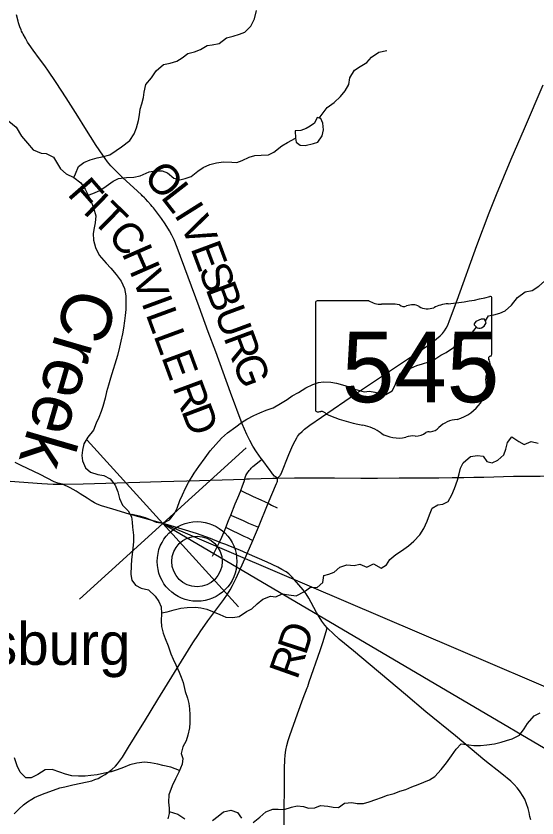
# Model space of a CAD drawing. Extents: x 0 to 70.2, y 0 to 31.4.
# Drawn here: x 5.768 to 6.741, y 16.713 to 18.211 of the extents above; entities that cross this region are included whole.
import ezdxf

# ---------------------------------------------------------------- set-up
doc = ezdxf.new("R2010")
doc.units = 0
for name, color, linetype in [('Default', 7, 'Continuous'), ('GM_X_County_Road', 7, 'Continuous'), ('GM_X_County_Road_Text', 7, 'Continuous'), ('GM_X_Minor_Lake', 7, 'Continuous'), ('GM_X_Minor_River', 7, 'Continuous'), ('GM_X_Minor_River_Text', 7, 'Continuous'), ('GM_X_State_Location', 7, 'Continuous'), ('GM_X_State_Route', 7, 'Continuous'), ('GM_X_State_Shield', 7, 'Continuous'), ('GM_X_Township_Road', 7, 'Continuous'), ('GM_X_Township_Road_Text', 7, 'Continuous'), ('GM_X_Unincorporated', 7, 'Continuous'), ('GM_X_Unincorporated_Location', 7, 'Continuous'), ('GM_X_Unincorporated_Text', 7, 'Continuous'), ('SH_Data', 7, 'Continuous')]:
    doc.layers.add(name, color=color, linetype=linetype)

msp = doc.modelspace()

# ---------------------------------------------------------------- linework, layer by layer
at = {"layer": 'Default'}
msp.add_lwpolyline([(7.3479, 16.7052), (6.0425, 17.2633), (7.3479, 16.4952)], close=True, dxfattribs=at)
at = {"layer": 'GM_X_County_Road'}
for points in [[(6.2277, 17.3831), (6.2266, 17.3845), (6.2176, 17.3972), (6.211, 17.4076), (6.2049, 17.4183), (6.1995, 17.4295), (6.1906, 17.4494), (6.1693, 17.5076), (6.1416, 17.5835), (6.1276, 17.6214), (6.1103, 17.668), (6.0694, 17.7787), (6.0635, 17.7931), (6.0595, 17.8016), (6.055, 17.8098), (6.047, 17.823), (6.0402, 17.8331), (6.0328, 17.843), (6.0251, 17.8525), (6.0227, 17.8552), (6.0201, 17.8586), (6.0145, 17.8648), (6.0102, 17.8695), (6.0083, 17.8715), (6.0041, 17.8754), (6.0028, 17.8768), (5.9877, 17.8905), (5.9677, 17.9089), (5.9552, 17.921), (5.9452, 17.9314), (5.9395, 17.9386), (5.9303, 17.9512), (5.9183, 17.969), (5.8968, 18.0026), (5.8837, 18.0239), (5.862, 18.058), (5.8433, 18.0867), (5.8276, 18.1097), (5.8233, 18.1158), (5.8131, 18.1304), (5.8084, 18.1362), (5.8039, 18.142), (5.8017, 18.1453), (5.796, 18.1532), (5.7901, 18.1624), (5.786, 18.1695), (5.7819, 18.1773), (5.7804, 18.1797), (5.7788, 18.183), (5.7778, 18.1854), (5.7758, 18.1907), (5.7733, 18.1985), (5.7724, 18.2014), (5.7694, 18.2133)], [(6.2568, 17.3479), (6.2532, 17.3501), (6.2509, 17.3519), (6.2476, 17.3559), (6.2451, 17.3595), (6.2433, 17.3621), (6.2277, 17.3831)]]:
    msp.add_lwpolyline(points, dxfattribs=at)
at = {"layer": 'GM_X_Minor_Lake'}
for points in [[(6.2906, 17.9827), (6.2917, 17.9751), (6.2992, 17.9698), (6.3087, 17.9694), (6.3239, 17.9727), (6.3323, 17.9753), (6.3403, 17.987), (6.3426, 17.9984), (6.3412, 18.011), (6.3378, 18.0197), (6.331, 18.0213), (6.326, 18.011), (6.318, 18.0054), (6.3104, 18.0012), (6.3005, 17.9971), (6.2895, 17.9964)], [(6.2895, 17.9964), (6.2906, 17.9827)], [(6.638, 17.6288), (6.6425, 17.6318), (6.6464, 17.6382), (6.6437, 17.6447), (6.6369, 17.6451), (6.627, 17.6406), (6.6243, 17.6361)], [(6.6243, 17.6361), (6.6244, 17.6341), (6.6257, 17.6324), (6.6279, 17.6302), (6.63, 17.6285), (6.6326, 17.628), (6.6355, 17.628), (6.638, 17.6288)]]:
    msp.add_lwpolyline(points, dxfattribs=at)
at = {"layer": 'GM_X_Minor_River'}
for points in [[(5.8762, 17.9092), (5.8797, 17.9164), (5.8851, 17.9297), (5.8953, 17.9376), (5.9071, 17.9421), (5.9201, 17.9462), (5.9295, 17.9481), (5.9436, 17.9518), (5.9554, 17.9601), (5.9657, 17.9669), (5.9809, 17.9782), (5.989, 17.9907), (5.9932, 18.0024), (5.997, 18.0157), (5.999, 18.0263), (6.0002, 18.0369), (6.0033, 18.0471), (6.0063, 18.0585), (6.0075, 18.0688), (6.0106, 18.0828), (6.0217, 18.0953), (6.0301, 18.1085), (6.0438, 18.1202), (6.0564, 18.1228), (6.0685, 18.1265), (6.0788, 18.1326), (6.0891, 18.1409), (6.1016, 18.1442), (6.1127, 18.1487), (6.1252, 18.1559), (6.1347, 18.157), (6.1476, 18.1599), (6.1617, 18.1705), (6.1742, 18.1735), (6.186, 18.1768), (6.1955, 18.1806), (6.207, 18.1923), (6.2139, 18.2059), (6.2173, 18.2211)], [(6.3345, 18.0204), (6.3493, 18.0401), (6.3626, 18.0492), (6.3744, 18.0605), (6.3832, 18.0711), (6.3901, 18.0832), (6.392, 18.0957), (6.4005, 18.1097), (6.4115, 18.1165), (6.4237, 18.1241), (6.4321, 18.1343), (6.4462, 18.1437), (6.4613, 18.1463)], [(5.7549, 18.0146), (5.7685, 18.0031), (5.7787, 17.9868), (5.7897, 17.9738), (5.8006, 17.9612), (5.8154, 17.9551), (5.8248, 17.9543), (5.8385, 17.9474), (5.8456, 17.9352), (5.8513, 17.9253), (5.8622, 17.9161), (5.8762, 17.9092), (5.8895, 17.8997), (5.8978, 17.8879), (5.9038, 17.8753), (5.9094, 17.8624), (5.9132, 17.8529), (5.9176, 17.838), (5.9164, 17.8248), (5.9141, 17.8153), (5.9122, 17.805), (5.9129, 17.7925), (5.9166, 17.7788), (5.9237, 17.7644), (5.9366, 17.7495), (5.9456, 17.74), (5.9554, 17.7281), (5.9645, 17.7156), (5.9709, 17.7019), (5.9738, 17.6886), (5.9738, 17.6776), (5.9733, 17.6628), (5.9725, 17.6514), (5.9713, 17.6419), (5.9694, 17.6282), (5.9674, 17.6172), (5.9643, 17.6036), (5.9616, 17.5926), (5.9577, 17.5767), (5.945, 17.5346), (5.9412, 17.5213), (5.9377, 17.5092), (5.935, 17.4975), (5.9304, 17.4819), (5.9273, 17.4724), (5.923, 17.4614), (5.9181, 17.4505), (5.9131, 17.4376), (5.9028, 17.4247), (5.8951, 17.4119), (5.8928, 17.4001), (5.8916, 17.3902), (5.8923, 17.38), (5.8979, 17.3671), (5.9078, 17.359), (5.921, 17.3548), (5.9324, 17.3528), (5.9441, 17.3467), (5.9539, 17.3349), (5.9588, 17.3223), (5.9618, 17.3098), (5.9674, 17.2972), (5.978, 17.2869), (5.9844, 17.2755), (5.9855, 17.266), (5.9862, 17.2562), (5.9876, 17.2417), (5.988, 17.2292), (5.9868, 17.2171), (5.9856, 17.2057), (5.984, 17.1951), (5.9832, 17.1848), (5.9827, 17.1681)], [(5.9031, 17.8766), (5.9118, 17.8798), (5.9251, 17.8851), (5.9369, 17.893), (5.9498, 17.9024), (5.9597, 17.9073), (5.9749, 17.9095), (5.9886, 17.9102), (6.0003, 17.9124), (6.0171, 17.9199), (6.0285, 17.9218), (6.0414, 17.9221), (6.0516, 17.9179), (6.0629, 17.9079), (6.0743, 17.9048), (6.0846, 17.9074), (6.0956, 17.9112), (6.1081, 17.9214), (6.1177, 17.9282), (6.1302, 17.9334), (6.1428, 17.9371), (6.156, 17.9386), (6.1716, 17.9378), (6.1811, 17.9377), (6.191, 17.9411), (6.2039, 17.9475), (6.2142, 17.9505), (6.2263, 17.9512), (6.24, 17.9519), (6.2502, 17.9567), (6.2651, 17.9684), (6.2757, 17.9748), (6.2906, 17.9827)], [(6.645, 17.6415), (6.6506, 17.6511), (6.6608, 17.653), (6.6719, 17.6563), (6.6821, 17.6604), (6.6939, 17.671), (6.705, 17.6854), (6.7191, 17.6956), (6.7324, 17.6985), (6.745, 17.7064), (6.7556, 17.7155), (6.7753, 17.7337)], [(5.9825, 17.2789), (5.9855, 17.2808), (5.9984, 17.2774), (6.0098, 17.2746), (6.0204, 17.27), (6.0303, 17.2658), (6.0435, 17.2639), (6.0549, 17.2702), (6.0645, 17.2816), (6.0691, 17.2918), (6.0745, 17.3062), (6.0794, 17.3168), (6.0848, 17.3289), (6.0906, 17.3395), (6.1013, 17.3573), (6.1101, 17.3698), (6.1219, 17.3857), (6.1311, 17.3989), (6.1414, 17.4107), (6.152, 17.4227), (6.1635, 17.4326), (6.1787, 17.4439), (6.1898, 17.4518), (6.1993, 17.4578), (6.2126, 17.465), (6.2236, 17.4698), (6.2358, 17.4747), (6.2487, 17.4792), (6.2624, 17.4875), (6.2746, 17.495), (6.2845, 17.5014), (6.2959, 17.5078), (6.31, 17.5165), (6.3225, 17.5229), (6.3332, 17.5263), (6.3427, 17.5277), (6.3563, 17.5269), (6.3669, 17.5253), (6.3783, 17.5222), (6.3908, 17.5184), (6.4014, 17.5142), (6.4185, 17.5091), (6.4287, 17.5106), (6.4389, 17.5087), (6.4495, 17.5052), (6.4594, 17.5044), (6.4712, 17.5112), (6.4766, 17.5218), (6.4804, 17.532), (6.4865, 17.5437), (6.4964, 17.5501), (6.5059, 17.5531), (6.5173, 17.558), (6.5276, 17.5617), (6.5394, 17.5651), (6.5504, 17.57), (6.5618, 17.5775), (6.5717, 17.5824), (6.5858, 17.5918), (6.5961, 17.5997), (6.6094, 17.613), (6.6212, 17.6205), (6.6283, 17.6298)], [(6.04, 17.0961), (6.0507, 17.0983), (6.0636, 17.1017), (6.0762, 17.105), (6.0883, 17.1065), (6.1035, 17.1068), (6.1133, 17.1056), (6.1247, 17.1033), (6.1353, 17.099), (6.1493, 17.0933), (6.1603, 17.0883), (6.1732, 17.0878), (6.185, 17.0897), (6.1987, 17.0991), (6.2086, 17.1036), (6.2189, 17.1131), (6.2292, 17.1217), (6.244, 17.1274), (6.2538, 17.1262), (6.2656, 17.1318), (6.2778, 17.1298), (6.2914, 17.1279), (6.307, 17.1365), (6.3184, 17.1441), (6.3309, 17.1436), (6.3412, 17.1531), (6.3432, 17.166), (6.3527, 17.1686), (6.3626, 17.1723), (6.3733, 17.1818), (6.3866, 17.1859), (6.4002, 17.185), (6.4105, 17.1873), (6.4237, 17.1819), (6.4363, 17.1879), (6.4506, 17.1799), (6.4605, 17.1863), (6.4663, 17.1961), (6.4781, 17.2055), (6.4887, 17.2123), (6.5013, 17.2214), (6.5112, 17.2301), (6.5227, 17.2421), (6.5299, 17.2539), (6.5361, 17.2675), (6.5407, 17.2796), (6.5457, 17.2918), (6.5563, 17.2982), (6.5658, 17.2996), (6.5753, 17.3045), (6.5822, 17.317), (6.5876, 17.3288), (6.593, 17.3443), (6.5961, 17.3557), (6.5988, 17.3667), (6.6037, 17.3765), (6.6171, 17.3886), (6.6304, 17.3904), (6.641, 17.3892), (6.6478, 17.3793), (6.6576, 17.3766), (6.6683, 17.3815), (6.6797, 17.3917), (6.6832, 17.4023), (6.6863, 17.4144), (6.6943, 17.425), (6.7075, 17.4162), (6.7174, 17.4105), (6.7303, 17.4161), (6.7439, 17.413)], [(5.9827, 17.1681), (5.9846, 17.1575), (5.9917, 17.1479), (6.002, 17.1426), (6.016, 17.1391), (6.0285, 17.1276), (6.0349, 17.1174), (6.0394, 17.1075), (6.0401, 17.0949), (6.0396, 17.0813), (6.0399, 17.071), (6.0433, 17.0585), (6.047, 17.0486), (6.0523, 17.0345), (6.0575, 17.0197), (6.062, 17.0098), (6.0669, 16.9992), (6.0729, 16.9858), (6.0771, 16.976), (6.0804, 16.9661), (6.0845, 16.9497), (6.0886, 16.9368), (6.0909, 16.9269), (6.0923, 16.917), (6.093, 16.9056), (6.093, 16.8908), (6.0922, 16.8814), (6.0891, 16.8677), (6.086, 16.8571), (6.0798, 16.8461), (6.0771, 16.8336), (6.0801, 16.8241), (6.0786, 16.8135), (6.0728, 16.7987), (6.0663, 16.7866), (6.0598, 16.7733), (6.054, 16.7567), (6.0532, 16.7426), (6.0543, 16.7316), (6.0542, 16.7214), (6.0519, 16.7119)], [(6.2112, 16.705), (6.2238, 16.7145), (6.2348, 16.725), (6.2478, 16.7299), (6.258, 16.7295), (6.2694, 16.729), (6.2827, 16.7335), (6.2933, 16.7357), (6.3055, 16.7346), (6.3149, 16.7318), (6.3267, 16.7322), (6.3373, 16.7363), (6.351, 16.7355), (6.3609, 16.7335), (6.3707, 16.7327), (6.3821, 16.7406), (6.3958, 16.7421), (6.4057, 16.7401), (6.4174, 16.7405), (6.4277, 16.7431), (6.4406, 16.7479), (6.4509, 16.7517), (6.4623, 16.7558), (6.4744, 16.7592), (6.4851, 16.7633), (6.4965, 16.7666), (6.5079, 16.7715), (6.5193, 16.776), (6.5299, 16.7801), (6.5406, 16.7846), (6.5505, 16.7907), (6.5627, 16.8035), (6.5722, 16.816), (6.5821, 16.8292), (6.5906, 16.8417), (6.6001, 16.8519), (6.6141, 16.8496), (6.6236, 16.8488), (6.6357, 16.8487), (6.6479, 16.8498), (6.6619, 16.852), (6.6745, 16.855), (6.6847, 16.858), (6.6954, 16.861), (6.7087, 16.8677), (6.7175, 16.8798), (6.7236, 16.8897), (6.7362, 16.904), (6.7472, 16.9097)], [(6.0739, 16.8016), (6.0573, 16.8079), (6.0429, 16.8114), (6.033, 16.8137), (6.0198, 16.8164), (6.0084, 16.8176), (5.9939, 16.8154), (5.981, 16.8124), (5.9689, 16.8076), (5.9571, 16.8034), (5.9464, 16.7993), (5.9335, 16.7967), (5.9202, 16.7941), (5.9081, 16.7927), (5.8974, 16.7916), (5.8853, 16.7916), (5.8728, 16.7921), (5.8607, 16.7952), (5.8504, 16.799), (5.8357, 16.8037), (5.8227, 16.803), (5.8094, 16.7943), (5.7965, 16.7883), (5.7866, 16.788), (5.7761, 16.799), (5.7708, 16.8108), (5.7656, 16.8253)], [(6.0542, 16.7252), (6.0709, 16.7205), (6.0838, 16.7117)], [(6.1357, 16.7084), (6.146, 16.7164), (6.1559, 16.7247), (6.1696, 16.728), (6.1821, 16.7234), (6.1896, 16.7127)]]:
    msp.add_lwpolyline(points, dxfattribs=at)
at = {"layer": 'GM_X_State_Route'}
for points in [[(6.2568, 17.3479), (6.2599, 17.3508), (6.2617, 17.3528), (6.2626, 17.3543), (6.2636, 17.3561), (6.2781, 17.3922), (6.2854, 17.4093), (6.2895, 17.4177), (6.2926, 17.4232), (6.2943, 17.4258), (6.2982, 17.4308), (6.3027, 17.4353), (6.3074, 17.4394), (6.3175, 17.4468), (6.4046, 17.5065), (6.4769, 17.5549), (6.5311, 17.5913), (6.5438, 17.6002), (6.5535, 17.6078), (6.5604, 17.6139), (6.5647, 17.6183), (6.5685, 17.6231), (6.5719, 17.6282), (6.5747, 17.6336), (6.5783, 17.6421), (6.5921, 17.68), (6.629, 17.7822), (6.652, 17.8432), (6.6659, 17.8778), (6.6935, 17.9437), (6.7179, 18.0009), (6.7531, 18.0827)], [(6.2002, 17.2073), (6.1863, 17.2133), (6.169, 17.2202), (6.1604, 17.2238), (6.1511, 17.2273), (6.1487, 17.2282), (6.1402, 17.2315), (6.1316, 17.235), (6.1052, 17.2443), (6.0786, 17.2528), (6.0518, 17.2606), (5.98, 17.2809), (5.949, 17.2899), (5.9279, 17.2964), (5.9197, 17.2994), (5.9147, 17.302), (5.9088, 17.3053), (5.9012, 17.3105), (5.8883, 17.3189), (5.8806, 17.3236), (5.8695, 17.3296), (5.8552, 17.3365), (5.8464, 17.3387), (5.8397, 17.3412), (5.8135, 17.3549), (5.7779, 17.3717), (5.7668, 17.3771)], [(5.7576, 17.3422), (5.8164, 17.3377), (5.838, 17.3367), (5.8552, 17.3365), (5.8597, 17.3365), (5.8938, 17.3371), (5.9994, 17.3404), (6.0398, 17.3414), (6.1112, 17.3437), (6.1955, 17.3462), (6.1989, 17.3464), (6.2043, 17.3466), (6.2478, 17.3476), (6.2538, 17.3478)], [(6.1091, 17.0557), (6.1125, 17.0608), (6.1268, 17.0812), (6.1565, 17.1211), (6.1636, 17.1313), (6.1685, 17.1391), (6.1729, 17.1473), (6.1794, 17.1613), (6.193, 17.1919), (6.1982, 17.2027), (6.2002, 17.2073), (6.2107, 17.2317), (6.2139, 17.2392), (6.221, 17.2561), (6.2396, 17.3009), (6.255, 17.338), (6.2561, 17.3406), (6.2565, 17.3423), (6.2567, 17.3441), (6.2568, 17.3479)], [(6.2538, 17.3478), (6.2568, 17.3479), (6.2885, 17.3482), (6.363, 17.3484), (6.4126, 17.3481), (6.4436, 17.3481), (6.4839, 17.3484), (6.518, 17.3486), (6.5397, 17.3487), (6.5583, 17.3487), (6.5831, 17.3489), (6.6048, 17.3493), (6.6235, 17.3497), (6.6421, 17.35), (6.6978, 17.3513), (6.7473, 17.3518), (6.7704, 17.352), (6.7786, 17.3521)], [(6.7297, 16.7099), (6.7284, 16.7161), (6.727, 16.7233), (6.7252, 16.7307), (6.722, 16.7395), (6.7186, 16.7481), (6.7145, 16.7553), (6.7115, 16.7601), (6.7091, 16.7639), (6.7046, 16.7696), (6.6986, 16.776), (6.6923, 16.7818), (6.6756, 16.7955), (6.6442, 16.8208), (6.5892, 16.8664), (6.534, 16.9116), (6.496, 16.9436), (6.3985, 17.0255), (6.3721, 17.0473), (6.3605, 17.0577), (6.3515, 17.0664), (6.3497, 17.0683), (6.3452, 17.0733), (6.3395, 17.0807), (6.3344, 17.0886), (6.3297, 17.0967), (6.3197, 17.1159), (6.3151, 17.1239), (6.3101, 17.1317), (6.3046, 17.1392), (6.2969, 17.1489), (6.2888, 17.1582), (6.2845, 17.1627), (6.2777, 17.1689), (6.273, 17.1727), (6.2652, 17.1775), (6.2572, 17.1818), (6.2377, 17.1912), (6.2002, 17.2073)], [(6.0082, 16.8937), (6.0334, 16.9343), (6.0774, 17.0058), (6.0987, 17.0401), (6.1091, 17.0557)], [(5.765, 16.7211), (5.7738, 16.7298), (5.7825, 16.7376), (5.7898, 16.7432), (5.7977, 16.7484), (5.8031, 16.7514), (5.8116, 16.7553), (5.823, 16.7598), (5.8383, 16.7654), (5.8505, 16.7693), (5.8596, 16.7717), (5.8748, 16.7751), (5.9011, 16.7805), (5.9101, 16.7828), (5.9159, 16.7848), (5.9216, 16.7871), (5.9271, 16.7898), (5.9351, 16.7944), (5.9402, 16.7979), (5.9474, 16.8037), (5.954, 16.8101), (5.9581, 16.8146), (5.9619, 16.8195), (5.9672, 16.8271), (5.9788, 16.8455), (6.0008, 16.8818), (6.0082, 16.8937)]]:
    msp.add_lwpolyline(points, dxfattribs=at)
at = {"layer": 'GM_X_State_Shield'}
for p, q in [((6.3278, 17.6756), (6.3278, 17.4755)), ((6.4275, 17.679), (6.331, 17.679)), ((6.6574, 17.5793), (6.6574, 17.684)), ((6.6573, 17.5793), (6.6574, 17.5793))]:
    msp.add_line(p, q, dxfattribs=at)
for centre, major_axis, start_param, end_param in [((6.3316, 17.676), (0.00382, 0), 1.712693, 3.28349), ((6.4505, 17.7023), (0.037, 0), 4.042523, 4.731795), ((6.4628, 17.5667), (0.133, 0), 1.404758, 1.657858), ((6.5087, 17.6539), (0.0222, 0), 0.950623, 2.079405), ((6.5845, 17.6179), (0.0703, 0), 1.699011, 2.107814), ((6.54, 17.9519), (0.3495, 0), 4.814394, 5.042369), ((6.6537, 17.6844), (0.00367, 0), 6.141152, 7.989035), ((6.493, 17.6771), (0.0107, 0), 3.836095, 5.185415), ((6.5373, 17.6856), (0.0267, 0), 4.081561, 5.145723), ((6.6565, 17.5716), (0.00568, 0), 1.883978, 3.671073), ((6.6204, 17.5584), (0.0341, 0), 5.934695, 6.695948), ((6.6534, 17.5789), (0.00393, 0), 5.05454, 6.418171), ((6.6705, 17.5355), (0.0248, 0), 2.387724, 3.262537), ((6.5595, 17.5222), (0.0874, 0), 5.101752, 6.440018), ((6.3316, 17.475), (0.00385, 0), 3.00124, 4.508301), ((6.3322, 17.4955), (0.0294, 0), 4.665946, 4.897461), ((6.3382, 17.4639), (0.0106, 0), 0.519207, 1.627899), ((6.472, 17.6437), (0.2524, 0), 4.195997, 4.488961), ((6.5964, 17.4193), (0.0479, 0), 1.647645, 2.488434), ((6.3968, 17.3856), (0.079, 0), 0.823519, 1.323587), ((6.5389, 17.4286), (0.00752, 0), 1.147584, 2.315152), ((6.5357, 17.4561), (0.0282, 0), 4.937069, 5.64225), ((6.4822, 17.4629), (0.0501, 0), 4.026481, 4.996735), ((6.5111, 17.3937), (0.0412, 0), 1.495662, 1.94098), ((6.5148, 17.4479), (0.0267, 0), 4.691044, 5.507374)]:
    msp.add_ellipse(centre, major_axis=major_axis, ratio=0.8, start_param=start_param, end_param=end_param, dxfattribs=at)
at = {"layer": 'GM_X_Township_Road'}
msp.add_line((6.1353, 17.2025), (6.1487, 17.2282), dxfattribs=at)
for points in [[(6.1955, 17.3462), (6.1961, 17.349), (6.1969, 17.351), (6.1979, 17.353), (6.1995, 17.3558), (6.2008, 17.358), (6.2027, 17.3606), (6.2037, 17.3619), (6.2061, 17.3647), (6.2077, 17.3665), (6.211, 17.3697), (6.2134, 17.3717), (6.2171, 17.3747), (6.2255, 17.3814), (6.2277, 17.3831)], [(6.1881, 17.3247), (6.1916, 17.3336), (6.1944, 17.3419), (6.1955, 17.3462)], [(6.1694, 17.2785), (6.1779, 17.2999), (6.1827, 17.3114), (6.1874, 17.3228), (6.1881, 17.3247)], [(6.1881, 17.3247), (6.1893, 17.3241), (6.2113, 17.3138), (6.2259, 17.3074), (6.2339, 17.3039), (6.2396, 17.3009)], [(6.2396, 17.3009), (6.2423, 17.2993), (6.2456, 17.2975), (6.2563, 17.2923)], [(6.1601, 17.2557), (6.1655, 17.2691), (6.1685, 17.2762), (6.1694, 17.2785)], [(6.1694, 17.2785), (6.1706, 17.278), (6.1838, 17.2727), (6.1925, 17.2688), (6.2028, 17.2641), (6.2179, 17.2574), (6.221, 17.2561)], [(6.1487, 17.2282), (6.1528, 17.2376), (6.1582, 17.251), (6.1601, 17.2557)], [(6.1601, 17.2557), (6.1619, 17.2549), (6.194, 17.2398), (6.2, 17.2368), (6.2081, 17.2329), (6.2107, 17.2317)], [(6.2699, 16.6727), (6.2694, 16.7195), (6.2699, 16.7782), (6.27, 16.8061), (6.2705, 16.8216), (6.2712, 16.8308), (6.2725, 16.8398), (6.2744, 16.8489), (6.2768, 16.8581), (6.2797, 16.867), (6.2944, 16.9078), (6.3049, 16.9369), (6.3122, 16.9562), (6.3132, 16.959), (6.3162, 16.9674), (6.3367, 17.0259), (6.3417, 17.0408), (6.3478, 17.0615), (6.3497, 17.0683)]]:
    msp.add_lwpolyline(points, dxfattribs=at)
at = {"layer": 'GM_X_Unincorporated'}
for radius in [0.0744, 0.0472]:
    msp.add_circle((6.1065, 17.1923), radius, dxfattribs=at)
at = {"layer": 'GM_X_Unincorporated_Location'}
msp.add_line((6.1065, 17.1923), (6.1065, 17.1923), dxfattribs=at)
at = {"layer": 'SH_Data'}
for p, q in [((6.1837, 17.1075), (5.9013, 17.419)), ((5.8867, 17.1221), (6.1982, 17.4045))]:
    msp.add_line(p, q, dxfattribs=at)

# ---------------------------------------------------------------- texts
at = {"layer": 'GM_X_County_Road_Text'}
for s, rotation, p in [('O', 312.4776, (6.0043, 17.9083)), ('F', 311.0357, (5.8627, 17.8777)), ('L', 307.8359, (6.0373, 17.8724)), ('I', 315.8009, (5.8914, 17.845)), ('T', 315.6819, (5.9081, 17.8288)), ('I', 302.1874, (6.0625, 17.84)), ('V', 294.0098, (6.0739, 17.8222)), ('C', 309.8321, (5.9375, 17.8002)), ('H', 293.6248, (5.9652, 17.768)), ('E', 290.376, (6.0939, 17.7774)), ('S', 290.3014, (6.1087, 17.7375)), ('V', 290.1919, (5.9849, 17.723)), ('B', 290.3002, (6.122, 17.7016)), ('I', 290.1705, (6.0021, 17.6761)), ('L', 290.1578, (6.0102, 17.6542)), ('U', 290.3027, (6.1382, 17.6578)), ('L', 290.1578, (6.0248, 17.6143)), ('R', 290.3053, (6.1555, 17.6109)), ('E', 290.1613, (6.0394, 17.5744)), ('G', 290.3002, (6.1717, 17.5672)), ('R', 290.2659, (6.0602, 17.518)), ('D', 290.7654, (6.0765, 17.4737))]:
    msp.add_text(s, height=0.0568, rotation=rotation, dxfattribs=at).set_placement(p)
at = {"layer": 'GM_X_Minor_River_Text'}
msp.add_text('Creek', height=0.09473, rotation=253.7653, dxfattribs=at).set_placement((5.868, 17.7076))
at = {"layer": 'GM_X_State_Location'}
for s in ['s', 'r']:
    msp.add_text(s, height=0.000189, dxfattribs=at).set_placement((6.4889, 17.5622))
msp.add_text('545', height=0.000189, rotation=0, dxfattribs=at).set_placement((6.422, 17.5484))
at = {"layer": 'GM_X_State_Shield'}
msp.add_text('545', height=0.13184, dxfattribs=at).set_placement((6.3769, 17.4896))
at = {"layer": 'GM_X_Township_Road_Text'}
for s, rotation, p in [('D', 72.1321, (6.3096, 17.0155)), ('R', 70.5047, (6.2934, 16.9698))]:
    msp.add_text(s, height=0.0568, rotation=rotation, dxfattribs=at).set_placement(p)
at = {"layer": 'GM_X_Unincorporated_Text'}
msp.add_text('Olivesburg', height=0.07898, rotation=0, dxfattribs=at).set_placement((5.4773, 16.9992))

doc.saveas('drawing.dxf')
